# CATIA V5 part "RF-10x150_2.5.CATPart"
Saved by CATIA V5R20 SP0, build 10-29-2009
Part number: _RF-10x150/2.5
Definition: NONE
Nomenclature: _RF-10x150/2.5
Source: Unknown
Description: PART-_RF-10x150/2.5-DESC
Bounding box of the stored display mesh (mm): x -150 to 22.5, y -5.9 to 5.9, z -5.9 to 5.9
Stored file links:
  C:\Users\Utente\Desktop\IO LAVORO\3D X SITO CF\X SITO\PLASTICA\RF\RF-10x150_2.5.CATPart
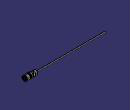
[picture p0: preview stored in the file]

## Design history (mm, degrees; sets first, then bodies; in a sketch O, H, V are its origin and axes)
Body1 "_RF-10x150/2.5" (main body)
  Solid1: solid without history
